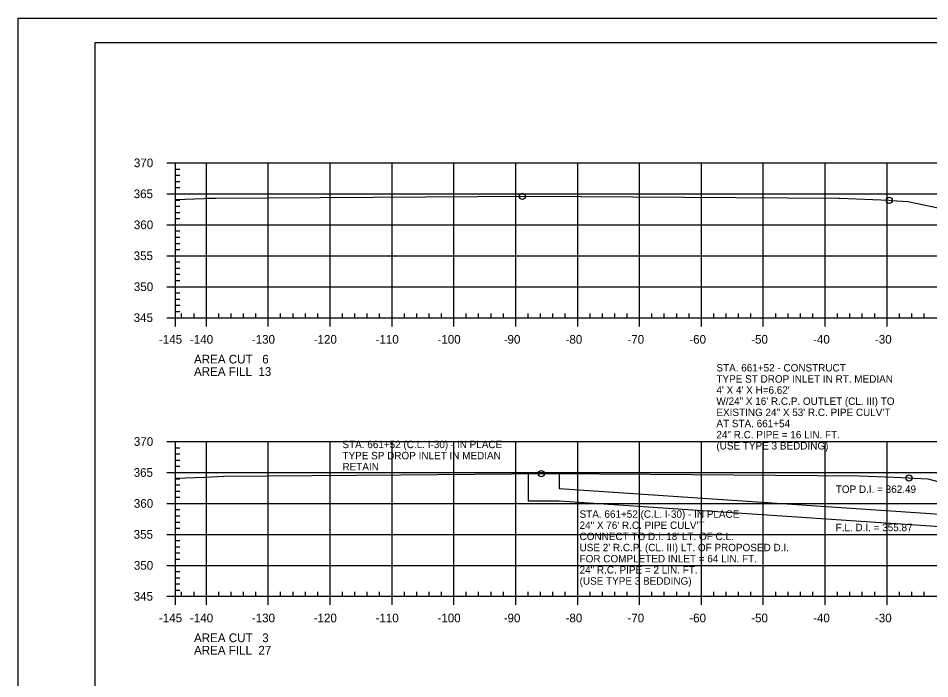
# Model space of a CAD drawing. Extents: x 1359801 to 1362404, y 372415 to 374228.
# Drawn here: x 1359800.9 to 1359948.3, y 373054.6 to 373161.3 of the extents above; entities that cross this region are included whole.
import ezdxf

# ---------------------------------------------------------------- set-up
doc = ezdxf.new("R2010")
doc.units = 0
for name, color, linetype in [('S_DRG_PT_SYM', 7, 'Continuous'), ('S_MAILBOX', 7, 'Continuous'), ('S_PRIMARY_CTL', 7, 'Continuous'), ('S_SHOULDER', 7, 'Continuous'), ('S_UTILITY_POLE_ANNOT', 7, 'Continuous'), ('S_UTL_PT_SYM', 7, 'Continuous'), ('S_WATER_UTILITIES', 7, 'Continuous')]:
    doc.layers.add(name, color=color, linetype=linetype)

msp = doc.modelspace()

# ---------------------------------------------------------------- linework, layer by layer
at = {"layer": 'S_DRG_PT_SYM'}
for points in [[(1359826.35, 373132), (1359831, 373132.19), (1359831.18, 373132.2), (1359832.87, 373132.21), (1359883.69, 373132.53), (1359933.56, 373132.23), (1359933.68, 373132.23), (1359933.76, 373132.23), (1359941.7, 373131.87), (1359942.09, 373131.85), (1359944.73, 373131.7), (1359956.83, 373129.13)], [(1359826.35, 373086.99), (1359831.15, 373087.18), (1359834.18, 373087.3), (1359862.77, 373087.54), (1359886.64, 373087.74), (1359903.04, 373087.63), (1359936.82, 373087.4), (1359942.48, 373087.14), (1359944.88, 373087.03), (1359945.74, 373086.98), (1359947.94, 373086.88), (1359956.9, 373084.51)]]:
    msp.add_lwpolyline(points, dxfattribs=at)
at = {"layer": 'S_MAILBOX'}
for p, q in [((1359826.35, 373137.92), (1360116.35, 373137.92)), ((1359826.35, 373112.92), (1359826.35, 373137.92)), ((1359831.35, 373112.92), (1359831.35, 373137.92)), ((1359841.35, 373112.92), (1359841.35, 373137.92)), ((1359851.35, 373112.92), (1359851.35, 373137.92)), ((1359861.35, 373112.92), (1359861.35, 373137.92)), ((1359871.35, 373112.92), (1359871.35, 373137.92)), ((1359881.35, 373112.92), (1359881.35, 373137.92)), ((1359891.35, 373112.92), (1359891.35, 373137.92)), ((1359901.35, 373112.92), (1359901.35, 373137.92)), ((1359911.35, 373112.92), (1359911.35, 373137.92)), ((1359921.35, 373112.92), (1359921.35, 373137.92)), ((1359931.35, 373112.92), (1359931.35, 373137.92)), ((1359941.35, 373112.92), (1359941.35, 373137.92)), ((1359826.35, 373132.92), (1360116.35, 373132.92)), ((1359826.35, 373127.92), (1360116.35, 373127.92)), ((1359826.35, 373122.92), (1360116.35, 373122.92)), ((1359826.35, 373117.92), (1360116.35, 373117.92)), ((1359826.35, 373112.92), (1360116.35, 373112.92)), ((1359826.35, 373092.92), (1360116.35, 373092.92)), ((1359826.35, 373067.92), (1359826.35, 373092.92)), ((1359831.35, 373067.92), (1359831.35, 373092.92)), ((1359841.35, 373067.92), (1359841.35, 373092.92)), ((1359851.35, 373067.92), (1359851.35, 373092.92)), ((1359861.35, 373067.92), (1359861.35, 373092.92)), ((1359871.35, 373067.92), (1359871.35, 373092.92)), ((1359881.35, 373067.92), (1359881.35, 373092.92)), ((1359891.35, 373067.92), (1359891.35, 373092.92)), ((1359901.35, 373067.92), (1359901.35, 373092.92)), ((1359911.35, 373067.92), (1359911.35, 373092.92)), ((1359921.35, 373067.92), (1359921.35, 373092.92)), ((1359931.35, 373067.92), (1359931.35, 373092.92)), ((1359941.35, 373067.92), (1359941.35, 373092.92)), ((1359826.35, 373087.92), (1360116.35, 373087.92)), ((1359826.35, 373082.92), (1360116.35, 373082.92)), ((1359826.35, 373077.92), (1360116.35, 373077.92)), ((1359826.35, 373072.92), (1360116.35, 373072.92)), ((1359826.35, 373067.92), (1360116.35, 373067.92))]:
    msp.add_line(p, q, dxfattribs=at)
at = {"layer": 'S_SHOULDER'}
msp.add_line((1359800.95, 373161.28), (1360134.28, 373161.28), dxfattribs=at)
for points in [[(1359800.94, 373161.28), (1360134.28, 373161.28), (1360134.28, 372947.94), (1359800.94, 372947.94)], [(1360047.27, 373157.38), (1360047.27, 373147.5), (1360083, 373147.5), (1360083, 373144.58), (1360106.2, 373144.58), (1360106.2, 373120.25), (1360129.53, 373120.25), (1360129.53, 372951.92), (1359813.35, 372951.92), (1359813.35, 373157.38)]]:
    msp.add_lwpolyline(points, close=True, dxfattribs=at)
for centre in [(1359882.41, 373132.52), (1359941.7, 373131.87), (1359885.46, 373087.73), (1359944.88, 373087.03)]:
    msp.add_circle(centre, 0.5, dxfattribs=at)
at = {"layer": 'S_UTILITY_POLE_ANNOT'}
for p, q in [((1359883.37, 373087.74), (1359883.37, 373083.34)), ((1359888.37, 373087.74), (1359888.37, 373085.34)), ((1359888.37, 373085.34), (1359951.53, 373081.07)), ((1359883.37, 373083.34), (1359888.37, 373083.34)), ((1359888.37, 373083.34), (1359951.53, 373079.07))]:
    msp.add_line(p, q, dxfattribs=at)
at = {"layer": 'S_UTL_PT_SYM'}
for p, q in [((1359813.35, 373157.38), (1360129.53, 373157.38)), ((1359813.35, 372951.92), (1359813.35, 373157.38))]:
    msp.add_line(p, q, dxfattribs=at)
at = {"layer": 'S_WATER_UTILITIES'}
for p, q in [((1359824.95, 373137.92), (1359826.35, 373137.92)), ((1359826.35, 373112.92), (1359826.35, 373137.92)), ((1359826.35, 373136.92), (1359827.05, 373136.92)), ((1359826.35, 373135.92), (1359827.05, 373135.92)), ((1359826.35, 373134.92), (1359827.05, 373134.92)), ((1359824.95, 373132.92), (1359826.35, 373132.92)), ((1359826.35, 373133.92), (1359827.05, 373133.92)), ((1359826.35, 373131.92), (1359827.05, 373131.92)), ((1359826.35, 373130.92), (1359827.05, 373130.92)), ((1359826.35, 373129.92), (1359827.05, 373129.92)), ((1359826.35, 373128.92), (1359827.05, 373128.92)), ((1359824.95, 373127.92), (1359826.35, 373127.92)), ((1359826.35, 373126.92), (1359827.05, 373126.92)), ((1359826.35, 373125.92), (1359827.05, 373125.92)), ((1359826.35, 373124.92), (1359827.05, 373124.92)), ((1359826.35, 373123.92), (1359827.05, 373123.92)), ((1359824.95, 373122.92), (1359826.35, 373122.92)), ((1359826.35, 373121.92), (1359827.05, 373121.92)), ((1359826.35, 373120.92), (1359827.05, 373120.92)), ((1359826.35, 373119.92), (1359827.05, 373119.92)), ((1359824.95, 373117.92), (1359826.35, 373117.92)), ((1359826.35, 373118.92), (1359827.05, 373118.92)), ((1359826.35, 373116.92), (1359827.05, 373116.92)), ((1359826.35, 373115.92), (1359827.05, 373115.92)), ((1359826.35, 373114.92), (1359827.05, 373114.92)), ((1359826.35, 373113.92), (1359827.05, 373113.92)), ((1359826.35, 373112.92), (1359826.35, 373113.62)), ((1359827.35, 373112.92), (1359827.35, 373113.62)), ((1359829.35, 373112.92), (1359829.35, 373113.62)), ((1359833.35, 373112.92), (1359833.35, 373113.62)), ((1359835.35, 373112.92), (1359835.35, 373113.62)), ((1359837.35, 373112.92), (1359837.35, 373113.62)), ((1359839.35, 373112.92), (1359839.35, 373113.62)), ((1359843.35, 373112.92), (1359843.35, 373113.62)), ((1359845.35, 373112.92), (1359845.35, 373113.62)), ((1359847.35, 373112.92), (1359847.35, 373113.62)), ((1359849.35, 373112.92), (1359849.35, 373113.62)), ((1359853.35, 373112.92), (1359853.35, 373113.62)), ((1359855.35, 373112.92), (1359855.35, 373113.62)), ((1359857.35, 373112.92), (1359857.35, 373113.62)), ((1359859.35, 373112.92), (1359859.35, 373113.62)), ((1359863.35, 373112.92), (1359863.35, 373113.62)), ((1359865.35, 373112.92), (1359865.35, 373113.62)), ((1359867.35, 373112.92), (1359867.35, 373113.62)), ((1359869.35, 373112.92), (1359869.35, 373113.62)), ((1359873.35, 373112.92), (1359873.35, 373113.62)), ((1359875.35, 373112.92), (1359875.35, 373113.62)), ((1359877.35, 373112.92), (1359877.35, 373113.62)), ((1359879.35, 373112.92), (1359879.35, 373113.62)), ((1359883.35, 373112.92), (1359883.35, 373113.62)), ((1359885.35, 373112.92), (1359885.35, 373113.62)), ((1359887.35, 373112.92), (1359887.35, 373113.62)), ((1359889.35, 373112.92), (1359889.35, 373113.62)), ((1359893.35, 373112.92), (1359893.35, 373113.62)), ((1359895.35, 373112.92), (1359895.35, 373113.62)), ((1359897.35, 373112.92), (1359897.35, 373113.62)), ((1359899.35, 373112.92), (1359899.35, 373113.62)), ((1359903.35, 373112.92), (1359903.35, 373113.62)), ((1359905.35, 373112.92), (1359905.35, 373113.62)), ((1359907.35, 373112.92), (1359907.35, 373113.62)), ((1359909.35, 373112.92), (1359909.35, 373113.62)), ((1359913.35, 373112.92), (1359913.35, 373113.62)), ((1359915.35, 373112.92), (1359915.35, 373113.62)), ((1359917.35, 373112.92), (1359917.35, 373113.62)), ((1359919.35, 373112.92), (1359919.35, 373113.62)), ((1359923.35, 373112.92), (1359923.35, 373113.62)), ((1359925.35, 373112.92), (1359925.35, 373113.62)), ((1359927.35, 373112.92), (1359927.35, 373113.62)), ((1359929.35, 373112.92), (1359929.35, 373113.62)), ((1359933.35, 373112.92), (1359933.35, 373113.62)), ((1359935.35, 373112.92), (1359935.35, 373113.62)), ((1359937.35, 373112.92), (1359937.35, 373113.62)), ((1359939.35, 373112.92), (1359939.35, 373113.62)), ((1359943.35, 373112.92), (1359943.35, 373113.62)), ((1359945.35, 373112.92), (1359945.35, 373113.62)), ((1359947.35, 373112.92), (1359947.35, 373113.62)), ((1359824.95, 373112.92), (1359826.35, 373112.92)), ((1359826.35, 373112.92), (1360116.35, 373112.92)), ((1359826.35, 373111.52), (1359826.35, 373112.92)), ((1359831.35, 373111.52), (1359831.35, 373112.92)), ((1359841.35, 373111.52), (1359841.35, 373112.92)), ((1359851.35, 373111.52), (1359851.35, 373112.92)), ((1359861.35, 373111.52), (1359861.35, 373112.92)), ((1359871.35, 373111.52), (1359871.35, 373112.92)), ((1359881.35, 373111.52), (1359881.35, 373112.92)), ((1359891.35, 373111.52), (1359891.35, 373112.92)), ((1359901.35, 373111.52), (1359901.35, 373112.92)), ((1359911.35, 373111.52), (1359911.35, 373112.92)), ((1359921.35, 373111.52), (1359921.35, 373112.92)), ((1359931.35, 373111.52), (1359931.35, 373112.92)), ((1359941.35, 373111.52), (1359941.35, 373112.92)), ((1359824.95, 373092.92), (1359826.35, 373092.92)), ((1359826.35, 373067.92), (1359826.35, 373092.92)), ((1359826.35, 373091.92), (1359827.05, 373091.92)), ((1359826.35, 373090.92), (1359827.05, 373090.92)), ((1359826.35, 373089.92), (1359827.05, 373089.92)), ((1359826.35, 373088.92), (1359827.05, 373088.92)), ((1359824.95, 373087.92), (1359826.35, 373087.92)), ((1359826.35, 373086.92), (1359827.05, 373086.92)), ((1359826.35, 373085.92), (1359827.05, 373085.92)), ((1359826.35, 373084.92), (1359827.05, 373084.92)), ((1359824.95, 373082.92), (1359826.35, 373082.92)), ((1359826.35, 373083.92), (1359827.05, 373083.92)), ((1359826.35, 373081.92), (1359827.05, 373081.92)), ((1359826.35, 373080.92), (1359827.05, 373080.92)), ((1359826.35, 373079.92), (1359827.05, 373079.92)), ((1359826.35, 373078.92), (1359827.05, 373078.92)), ((1359824.95, 373077.92), (1359826.35, 373077.92)), ((1359826.35, 373076.92), (1359827.05, 373076.92)), ((1359826.35, 373075.92), (1359827.05, 373075.92)), ((1359826.35, 373074.92), (1359827.05, 373074.92)), ((1359826.35, 373073.92), (1359827.05, 373073.92)), ((1359824.95, 373072.92), (1359826.35, 373072.92)), ((1359826.35, 373071.92), (1359827.05, 373071.92)), ((1359826.35, 373070.92), (1359827.05, 373070.92)), ((1359826.35, 373069.92), (1359827.05, 373069.92)), ((1359824.95, 373067.92), (1359826.35, 373067.92)), ((1359826.35, 373068.92), (1359827.05, 373068.92)), ((1359826.35, 373067.92), (1359826.35, 373068.62)), ((1359826.35, 373067.92), (1360116.35, 373067.92)), ((1359826.35, 373066.52), (1359826.35, 373067.92)), ((1359827.35, 373067.92), (1359827.35, 373068.62)), ((1359829.35, 373067.92), (1359829.35, 373068.62)), ((1359831.35, 373066.52), (1359831.35, 373067.92)), ((1359833.35, 373067.92), (1359833.35, 373068.62)), ((1359835.35, 373067.92), (1359835.35, 373068.62)), ((1359837.35, 373067.92), (1359837.35, 373068.62)), ((1359839.35, 373067.92), (1359839.35, 373068.62)), ((1359841.35, 373066.52), (1359841.35, 373067.92)), ((1359843.35, 373067.92), (1359843.35, 373068.62)), ((1359845.35, 373067.92), (1359845.35, 373068.62)), ((1359847.35, 373067.92), (1359847.35, 373068.62)), ((1359849.35, 373067.92), (1359849.35, 373068.62)), ((1359851.35, 373066.52), (1359851.35, 373067.92)), ((1359853.35, 373067.92), (1359853.35, 373068.62)), ((1359855.35, 373067.92), (1359855.35, 373068.62)), ((1359857.35, 373067.92), (1359857.35, 373068.62)), ((1359859.35, 373067.92), (1359859.35, 373068.62)), ((1359861.35, 373066.52), (1359861.35, 373067.92)), ((1359863.35, 373067.92), (1359863.35, 373068.62)), ((1359865.35, 373067.92), (1359865.35, 373068.62)), ((1359867.35, 373067.92), (1359867.35, 373068.62)), ((1359869.35, 373067.92), (1359869.35, 373068.62)), ((1359871.35, 373066.52), (1359871.35, 373067.92)), ((1359873.35, 373067.92), (1359873.35, 373068.62)), ((1359875.35, 373067.92), (1359875.35, 373068.62)), ((1359877.35, 373067.92), (1359877.35, 373068.62)), ((1359879.35, 373067.92), (1359879.35, 373068.62)), ((1359881.35, 373066.52), (1359881.35, 373067.92)), ((1359883.35, 373067.92), (1359883.35, 373068.62)), ((1359885.35, 373067.92), (1359885.35, 373068.62)), ((1359887.35, 373067.92), (1359887.35, 373068.62)), ((1359889.35, 373067.92), (1359889.35, 373068.62)), ((1359891.35, 373066.52), (1359891.35, 373067.92)), ((1359893.35, 373067.92), (1359893.35, 373068.62)), ((1359895.35, 373067.92), (1359895.35, 373068.62)), ((1359897.35, 373067.92), (1359897.35, 373068.62)), ((1359899.35, 373067.92), (1359899.35, 373068.62)), ((1359901.35, 373066.52), (1359901.35, 373067.92)), ((1359903.35, 373067.92), (1359903.35, 373068.62)), ((1359905.35, 373067.92), (1359905.35, 373068.62)), ((1359907.35, 373067.92), (1359907.35, 373068.62)), ((1359909.35, 373067.92), (1359909.35, 373068.62)), ((1359911.35, 373066.52), (1359911.35, 373067.92)), ((1359913.35, 373067.92), (1359913.35, 373068.62)), ((1359915.35, 373067.92), (1359915.35, 373068.62)), ((1359917.35, 373067.92), (1359917.35, 373068.62)), ((1359919.35, 373067.92), (1359919.35, 373068.62)), ((1359921.35, 373066.52), (1359921.35, 373067.92)), ((1359923.35, 373067.92), (1359923.35, 373068.62)), ((1359925.35, 373067.92), (1359925.35, 373068.62)), ((1359927.35, 373067.92), (1359927.35, 373068.62)), ((1359929.35, 373067.92), (1359929.35, 373068.62)), ((1359931.35, 373066.52), (1359931.35, 373067.92)), ((1359933.35, 373067.92), (1359933.35, 373068.62)), ((1359935.35, 373067.92), (1359935.35, 373068.62)), ((1359937.35, 373067.92), (1359937.35, 373068.62)), ((1359939.35, 373067.92), (1359939.35, 373068.62)), ((1359941.35, 373066.52), (1359941.35, 373067.92)), ((1359943.35, 373067.92), (1359943.35, 373068.62)), ((1359945.35, 373067.92), (1359945.35, 373068.62)), ((1359947.35, 373067.92), (1359947.35, 373068.62))]:
    msp.add_line(p, q, dxfattribs=at)

# ---------------------------------------------------------------- texts
at = {"layer": 'S_PRIMARY_CTL'}
for s, p in [('370', (1359819.63, 373137.22)), ('365', (1359819.6, 373132.22)), ('360', (1359819.63, 373127.22)), ('355', (1359819.6, 373122.22)), ('350', (1359819.63, 373117.22)), ('345', (1359819.6, 373112.22)), ('-145', (1359823.68, 373108.72)), ('-140', (1359828.69, 373108.72)), ('-130', (1359838.69, 373108.72)), ('-120', (1359848.69, 373108.72)), ('-110', (1359858.69, 373108.72)), ('-100', (1359868.69, 373108.72)), ('-90', (1359879.39, 373108.72)), ('-80', (1359889.39, 373108.72)), ('-70', (1359899.39, 373108.72)), ('-60', (1359909.39, 373108.72)), ('-50', (1359919.39, 373108.72)), ('-40', (1359929.39, 373108.72)), ('-30', (1359939.39, 373108.72)), ('AREA CUT   6', (1359829.35, 373105.52)), ('AREA FILL  13', (1359829.35, 373103.52)), ('370', (1359819.63, 373092.22)), ('365', (1359819.6, 373087.22)), ('360', (1359819.63, 373082.22)), ('355', (1359819.6, 373077.22)), ('350', (1359819.63, 373072.22)), ('345', (1359819.6, 373067.22)), ('-145', (1359823.68, 373063.72)), ('-140', (1359828.69, 373063.72)), ('-130', (1359838.69, 373063.72)), ('-120', (1359848.69, 373063.72)), ('-110', (1359858.69, 373063.72)), ('-100', (1359868.69, 373063.72)), ('-90', (1359879.39, 373063.72)), ('-80', (1359889.39, 373063.72)), ('-70', (1359899.39, 373063.72)), ('-60', (1359909.39, 373063.72)), ('-50', (1359919.39, 373063.72)), ('-40', (1359929.39, 373063.72)), ('-30', (1359939.39, 373063.72)), ('AREA CUT   3', (1359829.35, 373060.52)), ('AREA FILL  27', (1359829.35, 373058.52))]:
    msp.add_text(s, height=1.4, dxfattribs=at).set_placement(p)
at = {"layer": 'S_SHOULDER'}
for p in [(1359831.14, 373132.15), (1359933.64, 373132.18), (1359834.14, 373087.25), (1359936.78, 373087.35)]:
    msp.add_text('+', height=0.1, dxfattribs=at).set_placement(p)
at = {"layer": 'S_UTILITY_POLE_ANNOT'}
for s, p in [('STA. 661+52 - CONSTRUCT', (1359913.77, 373104.23)), ('TYPE ST DROP INLET IN RT. MEDIAN', (1359913.77, 373102.43)), ("4' X 4' X H=6.62'", (1359913.77, 373100.63)), ('W/24" X 16\' R.C.P. OUTLET (CL. III) TO ', (1359913.77, 373098.83)), ('EXISTING 24" X 53\' R.C. PIPE CULV\'T ', (1359913.77, 373097.03)), ('AT STA. 661+54', (1359913.77, 373095.23)), ('24" R.C. PIPE = 16 LIN. FT.', (1359913.77, 373093.43)), ('STA. 661+52 (C.L. I-30) - IN PLACE', (1359853.34, 373091.85)), ('(USE TYPE 3 BEDDING)', (1359913.77, 373091.63)), ('TYPE SP DROP INLET IN MEDIAN', (1359853.34, 373090.05)), ('RETAIN', (1359853.34, 373088.25)), ('TOP D.I. = 362.49', (1359933.06, 373084.62)), ('STA. 661+52 (C.L. I-30) - IN PLACE', (1359891.66, 373080.6)), ('24" X 76\' R.C. PIPE CULV\'T', (1359891.66, 373078.8)), ('F.L. D.I. = 355.87', (1359933.03, 373078.44)), ("CONNECT TO D.I. 18' LT. OF C.L.", (1359891.66, 373077)), ("USE 2' R.C.P. (CL. III) LT. OF PROPOSED D.I.", (1359891.66, 373075.2)), ('FOR COMPLETED INLET = 64 LIN. FT.', (1359891.66, 373073.4)), ('24" R.C. PIPE = 2 LIN. FT.', (1359891.66, 373071.6)), ('(USE TYPE 3 BEDDING)', (1359891.66, 373069.8))]:
    msp.add_text(s, height=1.2, dxfattribs=at).set_placement(p)

doc.saveas('drawing.dxf')
